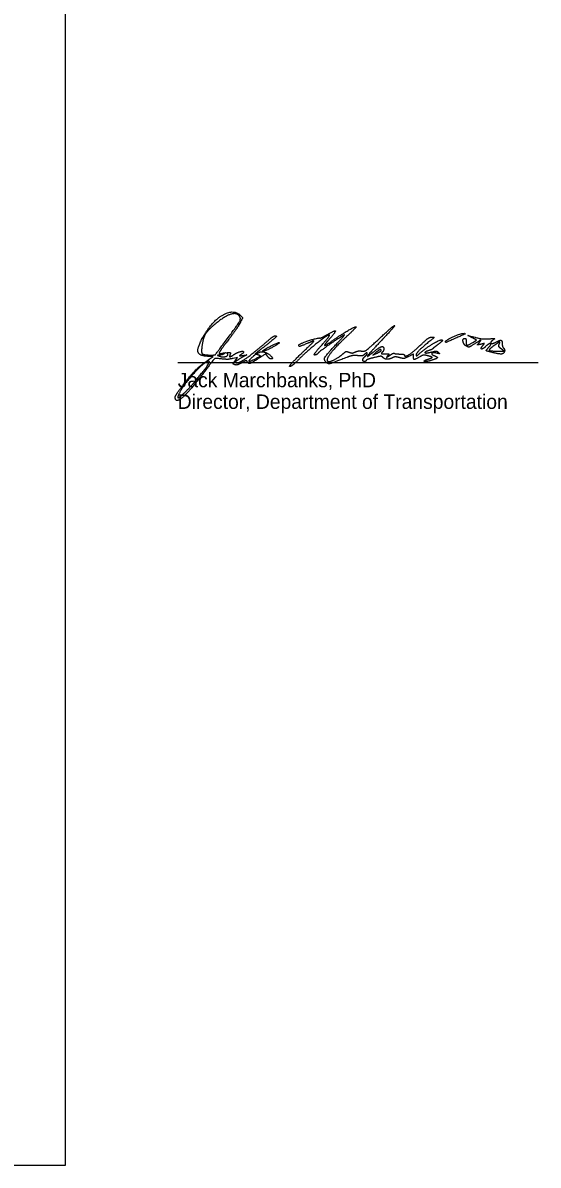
# Model space of a CAD drawing. Extents: x -8.3 to 42.1, y 0 to 22.
# Drawn here: x 33.59 to 38.59, y 0 to 11.1 of the extents above; entities that cross this region are included whole.
import ezdxf

# ---------------------------------------------------------------- set-up
doc = ezdxf.new("R2010")
doc.units = 0
for name, color, linetype in [('SH_Cut_Line', 7, 'Continuous'), ('SH_Data', 7, 'Continuous'), ('SH_Text', 7, 'Continuous')]:
    doc.layers.add(name, color=color, linetype=linetype)

msp = doc.modelspace()

# ---------------------------------------------------------------- linework, layer by layer
at = {"layer": 'SH_Cut_Line'}
msp.add_lwpolyline([(0, 0), (34, 0), (34, 22), (0, 22)], close=True, dxfattribs=at)
at = {"layer": 'SH_Data'}
msp.add_line((35.091, 7.797), (38.591, 7.797), dxfattribs=at)
at = {"layer": 'SH_Text'}
for p, q in [((35.553, 8.002), (35.553, 8.002)), ((37.692, 8.001), (37.692, 8.001)), ((35.918, 7.912), (35.918, 7.912)), ((36.29, 7.883), (36.29, 7.883)), ((37.067, 7.914), (37.067, 7.914)), ((38.145, 7.895), (38.145, 7.895)), ((35.874, 7.87), (35.874, 7.87))]:
    msp.add_line(p, q, dxfattribs=at)
for points in [[(37.956, 7.991), (37.993, 8.013), (37.952, 8.036)], [(37.016, 7.894), (36.986, 7.869), (37.027, 7.888)], [(38.205, 7.908), (38.261, 7.908), (38.232, 7.93)], [(35.405, 7.835), (35.436, 7.856), (35.398, 7.857)], [(35.648, 7.815), (35.67, 7.847), (35.628, 7.837)]]:
    msp.add_lwpolyline(points, dxfattribs=at)
for points in [[(35.342, 8.053), (35.428, 8.203), (35.636, 8.319), (35.702, 8.253)], [(35.693, 8.244), (35.667, 8.286), (35.541, 8.245), (35.445, 8.163)], [(35.553, 8.002), (35.674, 8.165), (35.707, 8.222), (35.693, 8.244)], [(35.702, 8.253), (35.721, 8.235), (35.721, 8.23), (35.702, 8.191)], [(35.445, 8.163), (35.379, 8.106), (35.34, 8.042), (35.329, 7.971)], [(35.702, 8.191), (35.691, 8.168), (35.64, 8.093), (35.587, 8.023)], [(36.537, 8.065), (36.615, 8.111), (36.628, 8.098), (36.568, 8.03)], [(36.596, 8.011), (36.676, 8.068), (36.807, 8.145), (36.823, 8.145)], [(36.823, 8.145), (36.828, 8.145), (36.787, 8.102), (36.731, 8.05)], [(37.05, 8.031), (37.125, 8.101), (37.191, 8.157), (37.197, 8.157)], [(37.197, 8.157), (37.202, 8.157), (37.15, 8.097), (37.081, 8.024)], [(35.398, 7.857), (35.3, 7.858), (35.277, 7.94), (35.342, 8.053)], [(35.407, 7.87), (35.454, 7.87), (35.458, 7.874), (35.553, 8.002)], [(35.587, 8.023), (35.535, 7.954), (35.492, 7.893), (35.492, 7.888)], [(35.918, 7.912), (35.939, 7.93), (36.071, 7.996), (36.076, 7.99)], [(36.076, 7.99), (36.082, 7.984), (35.94, 7.907), (35.922, 7.907)], [(35.932, 7.979), (35.982, 8.022), (36.028, 8.057), (36.033, 8.057)], [(36.033, 8.057), (36.058, 8.058), (36.034, 8.032), (35.949, 7.965)], [(36.565, 8.064), (36.555, 8.074), (36.345, 7.907), (36.267, 7.828)], [(36.268, 7.967), (36.268, 7.977), (36.455, 8.041), (36.471, 8.035)], [(36.29, 7.883), (36.361, 7.951), (36.417, 8.007), (36.413, 8.007)], [(36.413, 8.007), (36.41, 8.007), (36.381, 7.996), (36.349, 7.982)], [(36.705, 8.064), (36.656, 8.036), (36.467, 7.904), (36.454, 7.888)], [(36.471, 8.035), (36.476, 8.034), (36.506, 8.047), (36.537, 8.065)], [(36.487, 7.964), (36.533, 8.016), (36.568, 8.061), (36.565, 8.064)], [(36.568, 8.03), (36.54, 7.998), (36.517, 7.969), (36.517, 7.964)], [(36.517, 7.964), (36.517, 7.96), (36.553, 7.981), (36.596, 8.011)], [(36.731, 8.05), (36.632, 7.957), (36.542, 7.848), (36.542, 7.821)], [(36.64, 7.985), (36.686, 8.034), (36.715, 8.07), (36.705, 8.064)], [(36.875, 7.909), (36.908, 7.906), (36.932, 7.923), (37.05, 8.031)], [(37.081, 8.024), (36.951, 7.886), (36.919, 7.839), (37.001, 7.907)], [(37.53, 7.998), (37.456, 7.937), (37.405, 7.883), (37.405, 7.866)], [(37.439, 7.884), (37.493, 7.933), (37.64, 8.023), (37.657, 8.017)], [(37.458, 7.975), (37.503, 8.019), (37.54, 8.045), (37.558, 8.044)], [(37.558, 8.044), (37.582, 8.044), (37.579, 8.038), (37.53, 7.998)], [(37.657, 8.017), (37.665, 8.014), (37.65, 7.996), (37.623, 7.976)], [(37.692, 8.001), (37.692, 8.013), (37.845, 8.084), (37.864, 8.08)], [(37.764, 8.022), (37.701, 7.994), (37.692, 7.991), (37.692, 8.001)], [(37.864, 8.08), (37.885, 8.076), (37.886, 8.076), (37.764, 8.022)], [(37.893, 7.957), (37.867, 7.971), (37.856, 8.032), (37.88, 8.032)], [(37.88, 8.032), (37.887, 8.032), (37.892, 8.018), (37.892, 8.001)], [(37.892, 8.001), (37.892, 7.964), (37.907, 7.962), (37.956, 7.991)], [(37.952, 8.036), (37.909, 8.06), (37.908, 8.06), (38.011, 8.034)], [(38.016, 7.987), (38.04, 8.016), (38.024, 8.012), (37.968, 7.975)], [(38.011, 8.034), (38.032, 8.028), (38.077, 8.026), (38.111, 8.028)], [(38.111, 8.028), (38.166, 8.031), (38.171, 8.029), (38.151, 8.014)], [(38.151, 8.014), (38.122, 7.993), (38.145, 7.976), (38.179, 7.994)], [(38.213, 7.976), (38.223, 8.001), (38.214, 7.998), (38.152, 7.953)], [(38.179, 7.994), (38.219, 8.016), (38.242, 8.01), (38.242, 7.979)], [(35.329, 7.971), (35.317, 7.898), (35.339, 7.87), (35.407, 7.87)], [(35.492, 7.888), (35.492, 7.884), (35.508, 7.883), (35.527, 7.888)], [(35.542, 7.883), (35.532, 7.876), (35.512, 7.87), (35.499, 7.869)], [(35.503, 7.857), (35.533, 7.845), (35.589, 7.869), (35.571, 7.887)], [(35.527, 7.888), (35.552, 7.894), (35.556, 7.892), (35.542, 7.883)], [(35.571, 7.887), (35.567, 7.891), (35.573, 7.895), (35.585, 7.895)], [(35.585, 7.895), (35.6, 7.895), (35.605, 7.889), (35.6, 7.876)], [(35.636, 7.874), (35.665, 7.894), (35.73, 7.912), (35.73, 7.9)], [(35.671, 7.795), (35.694, 7.795), (35.82, 7.884), (35.932, 7.979)], [(35.73, 7.9), (35.73, 7.895), (35.72, 7.884), (35.708, 7.876)], [(35.949, 7.965), (35.855, 7.892), (35.834, 7.87), (35.878, 7.894)], [(35.878, 7.894), (35.89, 7.901), (35.914, 7.903), (35.931, 7.899)], [(35.964, 7.857), (35.947, 7.881), (35.945, 7.881), (35.879, 7.838)], [(35.922, 7.907), (35.917, 7.907), (35.916, 7.909), (35.918, 7.912)], [(35.931, 7.899), (35.967, 7.889), (36.025, 7.832), (35.999, 7.832)], [(36.18, 7.758), (36.17, 7.758), (36.219, 7.815), (36.29, 7.883)], [(36.349, 7.982), (36.286, 7.956), (36.267, 7.952), (36.268, 7.967)], [(36.421, 7.87), (36.411, 7.87), (36.44, 7.911), (36.487, 7.964)], [(36.454, 7.888), (36.446, 7.878), (36.431, 7.87), (36.421, 7.87)], [(36.533, 7.799), (36.507, 7.825), (36.536, 7.875), (36.64, 7.985)], [(36.56, 7.807), (36.582, 7.807), (36.663, 7.853), (36.7, 7.885)], [(36.7, 7.885), (36.72, 7.903), (36.733, 7.906), (36.757, 7.897)], [(36.757, 7.897), (36.777, 7.889), (36.796, 7.89), (36.812, 7.899)], [(36.812, 7.899), (36.825, 7.906), (36.854, 7.911), (36.875, 7.909)], [(36.93, 7.886), (36.93, 7.893), (36.92, 7.89), (36.907, 7.878)], [(36.911, 7.857), (36.921, 7.866), (36.93, 7.879), (36.93, 7.886)], [(37.001, 7.907), (37.05, 7.946), (37.092, 7.957), (37.092, 7.929)], [(37.067, 7.914), (37.067, 7.927), (37.043, 7.918), (37.016, 7.894)], [(37.027, 7.888), (37.049, 7.899), (37.067, 7.911), (37.067, 7.914)], [(37.077, 7.897), (37.066, 7.886), (37.072, 7.882), (37.104, 7.882)], [(37.092, 7.929), (37.092, 7.92), (37.086, 7.906), (37.077, 7.897)], [(37.104, 7.882), (37.141, 7.882), (37.144, 7.88), (37.128, 7.861)], [(37.15, 7.867), (37.171, 7.882), (37.192, 7.891), (37.196, 7.887)], [(37.196, 7.887), (37.2, 7.883), (37.223, 7.88), (37.248, 7.88)], [(37.248, 7.88), (37.272, 7.88), (37.292, 7.875), (37.292, 7.868)], [(37.292, 7.868), (37.292, 7.846), (37.388, 7.907), (37.458, 7.975)], [(37.405, 7.866), (37.405, 7.859), (37.42, 7.867), (37.439, 7.884)], [(37.533, 7.915), (37.483, 7.899), (37.503, 7.885), (37.555, 7.899)], [(37.567, 7.931), (37.564, 7.927), (37.548, 7.919), (37.533, 7.915)], [(37.555, 7.899), (37.593, 7.909), (37.608, 7.909), (37.62, 7.897)], [(37.602, 7.889), (37.565, 7.898), (37.552, 7.875), (37.586, 7.862)], [(37.623, 7.976), (37.596, 7.955), (37.571, 7.935), (37.567, 7.931)], [(37.62, 7.897), (37.633, 7.884), (37.63, 7.882), (37.602, 7.889)], [(37.968, 7.975), (37.928, 7.949), (37.915, 7.945), (37.893, 7.957)], [(38.035, 7.975), (38.002, 7.967), (38, 7.968), (38.016, 7.987)], [(38.055, 7.964), (38.07, 7.982), (38.068, 7.983), (38.035, 7.975)], [(38.084, 7.955), (38.052, 7.925), (38.029, 7.932), (38.055, 7.964)], [(38.109, 7.943), (38.14, 7.976), (38.118, 7.987), (38.084, 7.955)], [(38.145, 7.895), (38.09, 7.908), (38.084, 7.915), (38.109, 7.943)], [(38.152, 7.953), (38.109, 7.922), (38.125, 7.908), (38.205, 7.908)], [(38.263, 7.902), (38.255, 7.881), (38.214, 7.878), (38.145, 7.895)], [(38.232, 7.93), (38.212, 7.946), (38.206, 7.959), (38.213, 7.976)], [(38.242, 7.979), (38.242, 7.963), (38.249, 7.944), (38.257, 7.936)], [(38.257, 7.936), (38.264, 7.928), (38.267, 7.913), (38.263, 7.902)], [(35.398, 7.806), (35.377, 7.827), (35.159, 7.601), (35.113, 7.511)], [(35.155, 7.593), (35.232, 7.693), (35.312, 7.77), (35.405, 7.835)], [(35.183, 7.529), (35.25, 7.598), (35.406, 7.798), (35.398, 7.806)], [(35.487, 7.835), (35.453, 7.838), (35.441, 7.828), (35.365, 7.726)], [(35.499, 7.869), (35.476, 7.868), (35.477, 7.867), (35.503, 7.857)], [(35.628, 7.837), (35.587, 7.828), (35.565, 7.827), (35.487, 7.835)], [(35.6, 7.876), (35.591, 7.853), (35.604, 7.852), (35.636, 7.874)], [(35.647, 7.775), (35.629, 7.782), (35.629, 7.786), (35.648, 7.815)], [(35.714, 7.795), (35.688, 7.78), (35.658, 7.771), (35.647, 7.775)], [(35.715, 7.846), (35.664, 7.817), (35.644, 7.795), (35.671, 7.795)], [(35.708, 7.876), (35.689, 7.862), (35.691, 7.861), (35.724, 7.865)], [(35.765, 7.809), (35.762, 7.817), (35.743, 7.812), (35.714, 7.795)], [(35.724, 7.865), (35.761, 7.871), (35.761, 7.871), (35.715, 7.846)], [(35.879, 7.838), (35.811, 7.794), (35.773, 7.784), (35.765, 7.809)], [(35.821, 7.854), (35.776, 7.813), (35.787, 7.804), (35.846, 7.834)], [(35.874, 7.87), (35.856, 7.877), (35.84, 7.872), (35.821, 7.854)], [(35.846, 7.834), (35.892, 7.858), (35.895, 7.862), (35.874, 7.87)], [(35.999, 7.832), (35.989, 7.832), (35.974, 7.844), (35.964, 7.857)], [(36.267, 7.828), (36.23, 7.789), (36.19, 7.758), (36.18, 7.758)], [(36.732, 7.847), (36.586, 7.789), (36.551, 7.781), (36.533, 7.799)], [(36.542, 7.821), (36.542, 7.814), (36.55, 7.807), (36.56, 7.807)], [(36.838, 7.864), (36.809, 7.868), (36.769, 7.861), (36.732, 7.847)], [(36.907, 7.878), (36.892, 7.864), (36.87, 7.86), (36.838, 7.864)], [(36.904, 7.807), (36.886, 7.807), (36.89, 7.84), (36.911, 7.857)], [(36.922, 7.818), (36.919, 7.812), (36.911, 7.807), (36.904, 7.807)], [(36.998, 7.845), (36.96, 7.836), (36.926, 7.824), (36.922, 7.818)], [(37.083, 7.847), (37.072, 7.858), (37.052, 7.858), (36.998, 7.845)], [(37.179, 7.845), (37.148, 7.828), (37.101, 7.829), (37.083, 7.847)], [(37.128, 7.861), (37.116, 7.846), (37.123, 7.848), (37.15, 7.867)], [(37.244, 7.845), (37.217, 7.852), (37.194, 7.852), (37.179, 7.845)], [(37.333, 7.856), (37.295, 7.837), (37.277, 7.835), (37.244, 7.845)], [(37.38, 7.856), (37.38, 7.879), (37.379, 7.879), (37.333, 7.856)], [(37.442, 7.853), (37.397, 7.826), (37.38, 7.827), (37.38, 7.856)], [(37.525, 7.861), (37.486, 7.871), (37.469, 7.869), (37.442, 7.853)], [(37.561, 7.82), (37.514, 7.805), (37.467, 7.81), (37.511, 7.826)], [(37.511, 7.826), (37.525, 7.831), (37.545, 7.838), (37.555, 7.842)], [(37.555, 7.842), (37.566, 7.846), (37.555, 7.853), (37.525, 7.861)], [(37.586, 7.862), (37.617, 7.85), (37.608, 7.835), (37.561, 7.82)], [(35.365, 7.726), (35.212, 7.524), (35.067, 7.395), (35.067, 7.462)], [(35.067, 7.462), (35.067, 7.472), (35.107, 7.531), (35.155, 7.593)], [(35.113, 7.511), (35.081, 7.45), (35.113, 7.458), (35.183, 7.529)]]:
    msp.add_open_spline(points, degree=2, dxfattribs=at)

# ---------------------------------------------------------------- texts
for s, p in [('Jack Marchbanks, PhD', (35.091, 7.557)), ('Director, Department of Transportation', (35.091, 7.347))]:
    msp.add_text(s, height=0.14, dxfattribs=at).set_placement(p)

doc.saveas('drawing.dxf')
